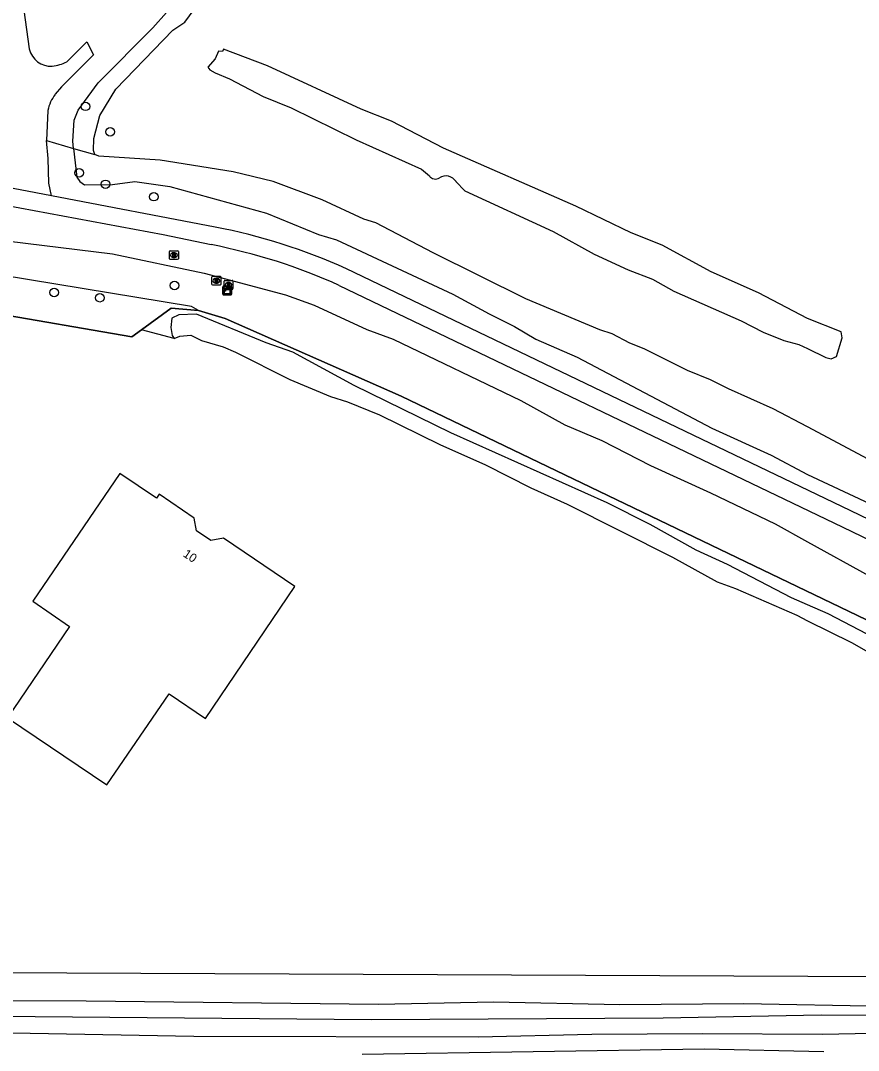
# Model space of a CAD drawing. Extents: x 162157 to 163165, y 378998 to 380775.
# Drawn here: x 162409.9 to 162505.8, y 379597.6 to 379715.5 of the extents above; entities that cross this region are included whole.
import ezdxf

# ---------------------------------------------------------------- set-up
doc = ezdxf.new("R2010")
doc.units = 0
for name, color, linetype in [('IMGEO_Boom', 7, 'Continuous'), ('IMGEO_Brandkraan', 7, 'Continuous'), ('IMGEO_Fietspad_gesloten', 7, 'Continuous'), ('IMGEO_Groenvoorziening', 7, 'Continuous'), ('IMGEO_Hek', 7, 'Continuous'), ('IMGEO_Kast', 7, 'Continuous'), ('IMGEO_Loofbos', 7, 'Continuous'), ('IMGEO_Muur', 7, 'Continuous'), ('IMGEO_Pand', 7, 'Continuous'), ('IMGEO_Pand_nummerreeks', 7, 'Continuous'), ('IMGEO_Rijbaan_lokaal_onverhard', 7, 'Continuous'), ('IMGEO_Rioolput', 7, 'Continuous'), ('IMGEO_Waterloop', 7, 'Continuous')]:
    doc.layers.add(name, color=color, linetype=linetype)

msp = doc.modelspace()

# ---------------------------------------------------------------- linework, layer by layer
at = {"layer": 'IMGEO_Boom'}
for centre in [(162417.36, 379705.69), (162420.18, 379702.78), (162416.63, 379698.09), (162419.64, 379696.77), (162425.19, 379695.35), (162427.56, 379685.19), (162413.77, 379684.37), (162419.01, 379683.78)]:
    msp.add_circle(centre, 0.489, dxfattribs=at)
at = {"layer": 'IMGEO_Brandkraan'}
for p, q in [((162426.99, 379688.24), (162426.99, 379689.09)), ((162427.06, 379689.16), (162427.91, 379689.16)), ((162427.99, 379689.09), (162427.99, 379688.24)), ((162427.91, 379688.16), (162427.06, 379688.16)), ((162427.5, 379688.38), (162427.47, 379688.38)), ((162427.48, 379688.94), (162427.5, 379688.94))]:
    msp.add_line(p, q, dxfattribs=at)
for points in [[(162426.99, 379688.24), (162426.99, 379689.09)], [(162427.06, 379689.16), (162427.91, 379689.16)], [(162427.99, 379689.09), (162427.99, 379688.24)], [(162427.91, 379688.16), (162427.06, 379688.16)], [(162427.33, 379688.86), (162427.33, 379688.46), (162427.55, 379688.46)], [(162427.57, 379688.86), (162427.33, 379688.86)], [(162427.51, 379688.78), (162427.46, 379688.78), (162427.46, 379688.71)], [(162427.46, 379688.71), (162427.51, 379688.71)], [(162427.52, 379688.63), (162427.46, 379688.63), (162427.46, 379688.55)], [(162427.46, 379688.55), (162427.52, 379688.55)]]:
    msp.add_lwpolyline(points, dxfattribs=at)
for centre, radius, start, end in [((162427.06, 379689.09), 0.0765, 91.552, 178.448), ((162427.06, 379689.09), 0.0765, 91.552, 178.448), ((162427.91, 379689.09), 0.0765, 1.552, 88.448), ((162427.91, 379689.09), 0.0765, 1.552, 88.448), ((162427.06, 379688.24), 0.0765, 181.552, 268.448), ((162427.06, 379688.24), 0.0765, 181.552, 268.448), ((162427.51, 379688.74), 0.0379, 267.8285, 90.9355), ((162427.52, 379688.59), 0.0404, 269.8759, 90.5077), ((162427.55, 379688.71), 0.251, 268.6676, 293.5347), ((162427.57, 379688.72), 0.145, 59.4692, 91.5367), ((162427.6, 379688.77), 0.0922, 285.5137, 58.1501), ((162427.6, 379688.57), 0.105, 301.3115, 78.989), ((162427.91, 379688.24), 0.0765, 271.552, 358.448), ((162427.91, 379688.24), 0.0765, 271.552, 358.448)]:
    msp.add_arc(centre, radius, start, end, dxfattribs=at)
for centre, major_axis, ratio, start_param, end_param in [((162427.47, 379688.66), (-0.387, 0.002), 0.722429, 4.712389, 7.853982), ((162427.5, 379688.66), (-0.39, 0.002), 0.717154, 1.570796, 4.712389)]:
    msp.add_ellipse(centre, major_axis=major_axis, ratio=ratio, start_param=start_param, end_param=end_param, dxfattribs=at)
at = {"layer": 'IMGEO_Fietspad_gesloten'}
for points in [[(162293.88, 379713.56), (162297.83, 379712.83), (162406.51, 379694.67), (162426.26, 379691.02), (162431.74, 379689.86)], [(162432.21, 379691.87), (162413.48, 379695.46)], [(162557.48, 379633.98), (162556.84, 379634.31), (162504.9, 379659.42), (162447.23, 379687.09)], [(162446.41, 379685.19), (162504, 379657.56), (162555.93, 379632.44), (162561.58, 379629.6)]]:
    msp.add_lwpolyline(points, dxfattribs=at)
for centre, radius, start, end in [((162419.44, 379625.71), 67.38, 65.6396, 79.0765), ((162418.79, 379623.79), 67.33, 65.7839, 78.9097)]:
    msp.add_arc(centre, radius, start, end, dxfattribs=at)
at = {"layer": 'IMGEO_Groenvoorziening'}
for points in [[(162423.76, 379680.09), (162422.68, 379679.3), (162406.25, 379682.13), (162347.07, 379692.29), (162343.87, 379688.35), (162342.56, 379688.42)], [(162430.28, 379682.33), (162427.17, 379682.58), (162423.76, 379680.09)], [(162427.51, 379679.13), (162423.76, 379680.09)], [(162217.87, 379605.5), (162247.08, 379605.11), (162255.15, 379605.08), (162262.9, 379605.2), (162282.05, 379605.15), (162289.85, 379605.22), (162308.4, 379605.53), (162313.87, 379605.74), (162332.41, 379605.9), (162337.03, 379605.95), (162352.97, 379606.09), (162363.72, 379605.88), (162374.72, 379605.85), (162378.4, 379605.96), (162380.44, 379606.31), (162381.21, 379606.63), (162576.44, 379605.74), (162576.49, 379606.38)], [(162583.87, 379601.63), (162573.91, 379602.07), (162557.68, 379602.05), (162525.01, 379602.55), (162508.94, 379602.64), (162492.71, 379602.92), (162478.54, 379602.81), (162464.08, 379603.1), (162450.91, 379602.84), (162417.45, 379603.23), (162402.03, 379603.27), (162387.27, 379603.21), (162374.55, 379603.06), (162361.54, 379603.25), (162327.73, 379603.13), (162310.18, 379603.37), (162273.39, 379603.64), (162254.33, 379604.29), (162234.09, 379604.68), (162224.23, 379605.14), (162217.88, 379605.23), (162217.87, 379605.5)], [(162501.89, 379597.42), (162488.2, 379597.72), (162449.03, 379597.12)]]:
    msp.add_lwpolyline(points, dxfattribs=at)
at = {"layer": 'IMGEO_Hek'}
for points in [[(162406.25, 379682.13), (162422.68, 379679.3), (162423.76, 379680.09)], [(162423.76, 379680.09), (162427.17, 379682.58), (162430.28, 379682.33)], [(162430.28, 379682.33), (162433.35, 379681.42), (162453.48, 379672.51), (162537.26, 379632.25), (162548.18, 379626.94), (162556.22, 379622.82), (162565.4, 379617.82), (162571.38, 379614.13), (162576.79, 379610.34)]]:
    msp.add_lwpolyline(points, dxfattribs=at)
at = {"layer": 'IMGEO_Kast'}
for p, q in [((162433.08, 379684.18), (162433.08, 379685.02)), ((162433.08, 379685.02), (162433.08, 379684.18)), ((162433.15, 379685.11), (162433.99, 379685.11)), ((162433.99, 379685.11), (162433.15, 379685.11)), ((162434.08, 379685.03), (162434.08, 379684.19)), ((162434.08, 379684.19), (162434.08, 379685.03)), ((162434, 379684.11), (162433.16, 379684.11)), ((162433.16, 379684.11), (162434, 379684.11))]:
    msp.add_line(p, q, dxfattribs=at)
for points in [[(162433.27, 379684.9), (162433.87, 379684.9), (162433.87, 379684.81), (162433.27, 379684.81), (162433.27, 379684.9)], [(162433.27, 379684.72), (162433.87, 379684.72), (162433.87, 379684.24), (162433.27, 379684.24), (162433.27, 379684.72)]]:
    msp.add_lwpolyline(points, dxfattribs=at)
msp.add_circle((162433.36, 379684.57), 0.0377, dxfattribs=at)
for centre, start, end in [((162433.16, 379685.03), 92.4484, 184.2845), ((162433.16, 379685.03), 92.4484, 184.2845), ((162434, 379685.03), 2.4484, 94.2845), ((162434, 379685.03), 2.4484, 94.2845), ((162433.16, 379684.19), 182.4484, 274.2845), ((162433.16, 379684.19), 182.4484, 274.2845), ((162434, 379684.19), 272.4484, 4.2845), ((162434, 379684.19), 272.4484, 4.2845)]:
    msp.add_arc(centre, 0.0779, start, end, dxfattribs=at)
at = {"layer": 'IMGEO_Loofbos'}
for points in [[(162412.89, 379701.78), (162415.99, 379700.88)], [(162430.28, 379682.33), (162429.51, 379682.78), (162345.56, 379696.61)], [(162406.42, 379690.54), (162420.47, 379688.81), (162430.94, 379686.6), (162440.24, 379684.12), (162443.52, 379682.91), (162449.55, 379680.16), (162452.58, 379679.03), (162467.18, 379672.02), (162472.24, 379669.23), (162476.49, 379667.45), (162482.03, 379664.56), (162488.91, 379661.45), (162496.32, 379657.89), (162500, 379655.84), (162507.07, 379651.92), (162527, 379642.12), (162536.23, 379637.93), (162571.68, 379620.55), (162577.82, 379616.97), (162589.02, 379609.76), (162590.32, 379608.63)], [(162576.79, 379610.34), (162571.38, 379614.13), (162565.4, 379617.82), (162556.22, 379622.82), (162548.18, 379626.94), (162537.26, 379632.25), (162453.48, 379672.51), (162433.35, 379681.42), (162430.28, 379682.33)]]:
    msp.add_lwpolyline(points, dxfattribs=at)
at = {"layer": 'IMGEO_Muur'}
msp.add_lwpolyline([(162381.21, 379606.63), (162576.44, 379605.74), (162576.49, 379606.38)], dxfattribs=at)
at = {"layer": 'IMGEO_Pand'}
msp.add_lwpolyline([(162408.42, 379635.69), (162419.81, 379628), (162426.95, 379638.44), (162431.1, 379635.6), (162441.34, 379650.7), (162433.15, 379656.25), (162431.71, 379655.98), (162430.06, 379657.09), (162429.79, 379658.54), (162425.79, 379661.28), (162425.48, 379660.81), (162421.29, 379663.64), (162411.33, 379649.02), (162415.52, 379646.14), (162408.42, 379635.69)], dxfattribs=at)
at = {"layer": 'IMGEO_Rijbaan_lokaal_onverhard'}
for points in [[(162407.91, 379787.07), (162404.33, 379784.27), (162403, 379782.61), (162402.58, 379781.28), (162405.36, 379754.24), (162407.92, 379733.94), (162410.93, 379712.28)], [(162415.21, 379710.79), (162417.5, 379713.07), (162418.27, 379711.58), (162414.63, 379707.93), (162413.9, 379707.07)], [(162413.05, 379705.23), (162412.89, 379701.78)], [(162413.48, 379695.46), (162413.18, 379696.91), (162413.08, 379699.72), (162412.89, 379701.78)], [(162413.48, 379695.46), (162407.26, 379696.65), (162406.55, 379696.77), (162403.9, 379697.22)]]:
    msp.add_lwpolyline(points, dxfattribs=at)
for centre, radius, start, end in [((162413.41, 379712.84), 2.55, 192.822, 273.2988), ((162413.15, 379714.75), 4.46, 275.2213, 297.5353), ((162417.24, 379704.4), 4.27, 141.4627, 168.8525)]:
    msp.add_arc(centre, radius, start, end, dxfattribs=at)
at = {"layer": 'IMGEO_Rioolput'}
for p, q in [((162431.84, 379685.31), (162431.84, 379686.16)), ((162431.92, 379686.24), (162432.77, 379686.24)), ((162432.33, 379686.01), (162432.36, 379686.01)), ((162432.85, 379686.16), (162432.85, 379685.31)), ((162433.23, 379684.83), (162433.23, 379685.68)), ((162433.31, 379685.75), (162434.16, 379685.75)), ((162434.23, 379685.68), (162434.23, 379684.83)), ((162432.77, 379685.23), (162431.92, 379685.23)), ((162432.35, 379685.46), (162432.33, 379685.46)), ((162434.16, 379684.75), (162433.31, 379684.75)), ((162433.72, 379685.53), (162433.75, 379685.53)), ((162433.74, 379684.97), (162433.72, 379684.97))]:
    msp.add_line(p, q, dxfattribs=at)
for points in [[(162431.84, 379685.31), (162431.84, 379686.16)], [(162431.92, 379686.24), (162432.77, 379686.24)], [(162432.43, 379685.93), (162432.18, 379685.93), (162432.18, 379685.53)], [(162432.18, 379685.53), (162432.31, 379685.53), (162432.31, 379685.7), (162432.32, 379685.7)], [(162432.36, 379685.85), (162432.31, 379685.85), (162432.31, 379685.77)], [(162432.31, 379685.77), (162432.36, 379685.77)], [(162432.36, 379685.67), (162432.43, 379685.53), (162432.57, 379685.53), (162432.51, 379685.66)], [(162432.85, 379686.16), (162432.85, 379685.31)], [(162433.23, 379684.83), (162433.23, 379685.68)], [(162433.31, 379685.75), (162434.16, 379685.75)], [(162434.23, 379685.68), (162434.23, 379684.83)], [(162432.77, 379685.23), (162431.92, 379685.23)], [(162434.16, 379684.75), (162433.31, 379684.75)], [(162433.82, 379685.45), (162433.57, 379685.45), (162433.57, 379685.05)], [(162433.57, 379685.05), (162433.69, 379685.05), (162433.69, 379685.21), (162433.71, 379685.21)], [(162433.75, 379685.37), (162433.69, 379685.37), (162433.69, 379685.29)], [(162433.69, 379685.29), (162433.75, 379685.29)], [(162433.75, 379685.18), (162433.82, 379685.05), (162433.96, 379685.05), (162433.9, 379685.18)]]:
    msp.add_lwpolyline(points, dxfattribs=at)
for centre, radius, start, end in [((162431.92, 379686.16), 0.0765, 91.552, 178.448), ((162431.92, 379686.16), 0.0765, 91.552, 178.448), ((162432.31, 379685.64), 0.0533, 26.0293, 88.6989), ((162432.36, 379685.76), 0.0964, 77.0061, 93.1865), ((162432.34, 379685.96), 0.19, 274.7715, 282.9687), ((162432.38, 379685.81), 0.0378, 276.6634, 79.6772), ((162432.43, 379685.82), 0.109, 350.3612, 89.416), ((162432.43, 379685.82), 0.112, 277.5842, 350.9817), ((162432.41, 379685.61), 0.108, 29.5134, 73.7905), ((162432.77, 379686.16), 0.0765, 1.552, 88.448), ((162432.77, 379686.16), 0.0765, 1.552, 88.448), ((162433.31, 379685.68), 0.0765, 91.552, 178.448), ((162433.31, 379685.68), 0.0765, 91.552, 178.448), ((162434.16, 379685.68), 0.0765, 1.552, 88.448), ((162434.16, 379685.68), 0.0765, 1.552, 88.448), ((162431.92, 379685.31), 0.0765, 181.552, 268.448), ((162431.92, 379685.31), 0.0765, 181.552, 268.448), ((162432.77, 379685.31), 0.0765, 271.552, 358.448), ((162432.77, 379685.31), 0.0765, 271.552, 358.448), ((162433.31, 379684.83), 0.0765, 181.552, 268.448), ((162433.31, 379684.83), 0.0765, 181.552, 268.448), ((162433.7, 379685.16), 0.0533, 26.0293, 88.6989), ((162433.75, 379685.27), 0.0964, 77.0061, 93.1865), ((162433.73, 379685.48), 0.19, 274.7715, 282.9687), ((162433.77, 379685.33), 0.0378, 276.6634, 79.6772), ((162433.82, 379685.34), 0.109, 350.3612, 89.416), ((162433.82, 379685.34), 0.112, 277.5842, 350.9817), ((162433.8, 379685.12), 0.108, 29.5134, 73.7905), ((162434.16, 379684.83), 0.0765, 271.552, 358.448), ((162434.16, 379684.83), 0.0765, 271.552, 358.448)]:
    msp.add_arc(centre, radius, start, end, dxfattribs=at)
for centre, major_axis, ratio, start_param, end_param in [((162432.33, 379685.73), (-0.387, 0.002), 0.722429, 4.712389, 7.853982), ((162432.36, 379685.73), (-0.39, 0.002), 0.717154, 1.570796, 4.712389), ((162433.72, 379685.25), (-0.387, 0.002), 0.722429, 4.712389, 7.853982), ((162433.74, 379685.25), (-0.39, 0.002), 0.717154, 1.570796, 4.712389)]:
    msp.add_ellipse(centre, major_axis=major_axis, ratio=ratio, start_param=start_param, end_param=end_param, dxfattribs=at)
at = {"layer": 'IMGEO_Waterloop'}
for points in [[(162418.41, 379700.17), (162418.29, 379700.63), (162418.33, 379702.03), (162419.01, 379704.63), (162420.85, 379707.67), (162427.37, 379714.42), (162428.73, 379715.33), (162429.81, 379716.79), (162431.87, 379718.53), (162435.73, 379722.44), (162436.81, 379724.52), (162437.81, 379727.6), (162438.09, 379730.39), (162437.87, 379732.15), (162436.61, 379736.13), (162434.68, 379739.75), (162433.34, 379741.62), (162431.94, 379744.12), (162431.35, 379745.64), (162430.75, 379748.23), (162430.6, 379750), (162430.81, 379753.63), (162433.19, 379759.73)], [(162415.99, 379700.88), (162415.9, 379701.72), (162416.07, 379704.11), (162416.53, 379705.25), (162418.82, 379708.37), (162425.07, 379714.68), (162428.19, 379718.23), (162429.87, 379719.79), (162431.45, 379721.79), (162433.88, 379726.03), (162434.41, 379727.38), (162434.93, 379729.62), (162434.96, 379731.45), (162434.82, 379732.58), (162434.21, 379734.79), (162431.84, 379739.92), (162430.72, 379741.38), (162429.29, 379744.28), (162428.39, 379748.48), (162428.43, 379750), (162428.47, 379751.52)], [(162459.77, 379697.07), (162460.78, 379696.01), (162470.9, 379691.35), (162475.6, 379688.76), (162479.47, 379686.98), (162482.26, 379685.92), (162484.72, 379684.55), (162492.41, 379681.12), (162494.95, 379679.84), (162497.3, 379678.9), (162499.02, 379678.44), (162500, 379677.97), (162502.13, 379676.94), (162502.74, 379676.79), (162503.32, 379677.05), (162503.98, 379679.17), (162503.86, 379679.87), (162500, 379681.42), (162494.39, 379684.33), (162488.98, 379686.75), (162483.39, 379689.79), (162479.83, 379691.22), (162473.48, 379694.26), (162458.35, 379700.92), (162452.41, 379704.01), (162448.92, 379705.39), (162438.21, 379710.32), (162433.16, 379712.25), (162433.03, 379711.98), (162432.6, 379712.03), (162432.21, 379711.14), (162431.36, 379710.19), (162431.61, 379709.88), (162432.22, 379709.52), (162433.86, 379708.86), (162437.69, 379706.82), (162440.91, 379705.54), (162448.35, 379701.85), (162455.84, 379698.5), (162456.73, 379697.74)], [(162415.99, 379700.88), (162418.41, 379700.17)], [(162415.99, 379700.88), (162416.35, 379697.6), (162416.72, 379697.08), (162417.25, 379696.71), (162420.45, 379696.73), (162423.01, 379697.07), (162427.01, 379696.5), (162438.08, 379693.47), (162444.05, 379691.02), (162446.1, 379690.4), (162459.42, 379684.2), (162463.56, 379681.92), (162466.49, 379680.5), (162468.93, 379679.03), (162473.64, 379676.97), (162489.06, 379668.85), (162495.85, 379665.75), (162500, 379663.53), (162509.49, 379659.13)], [(162525.17, 379656.9), (162522.66, 379657.86), (162516.28, 379660.79), (162512.53, 379662.77), (162508.68, 379664.39), (162500, 379668.98), (162496.1, 379671.04), (162490.98, 379673.33), (162488.93, 379674.39), (162486.27, 379675.43), (162481.32, 379677.92), (162479.66, 379678.58), (162477.66, 379679.66), (162476.24, 379680.12), (162467.78, 379683.67), (162457.18, 379688.91), (162450.6, 379692.37), (162449.24, 379692.79), (162444.45, 379695), (162438.86, 379697.09), (162434.27, 379698.21), (162425.92, 379699.54), (162418.87, 379700), (162418.41, 379700.17)], [(162526.23, 379634.14), (162526.72, 379635.02), (162526.82, 379635.76), (162525.74, 379636.78), (162522.64, 379638.06), (162506.86, 379645.24), (162502.39, 379647.6), (162500, 379648.62), (162498.17, 379649.41), (162490.86, 379653.23), (162487.26, 379654.89), (162482.01, 379657.8), (162477.08, 379660.29), (162459.17, 379668.3), (162448.12, 379673.72), (162441.1, 379677.53), (162438.03, 379678.63), (162430.05, 379681.9), (162428.03, 379681.84), (162427.24, 379681.45), (162427.13, 379680.38), (162427.28, 379679.47), (162427.51, 379679.13)], [(162427.51, 379679.13), (162428.15, 379679.38), (162429.43, 379679.48), (162430.65, 379678.9), (162433.12, 379678.16), (162434.55, 379677.53), (162440.74, 379674.41), (162445.4, 379672.46), (162447.34, 379671.86), (162451, 379670.36), (162457.94, 379666.98), (162463.16, 379664.66), (162468.34, 379662), (162472.51, 379660.13), (162484.57, 379654.08), (162489.68, 379651.24), (162491.76, 379650.47), (162498.81, 379647.43), (162500, 379646.77), (162505.07, 379644.31), (162510.75, 379641.07)], [(162390.14, 379601.66), (162450.09, 379601.12), (162483.49, 379601.33), (162501.57, 379601.68), (162517.5, 379601.59), (162533.57, 379601.39), (162564.43, 379600.52), (162577.81, 379600.87), (162587.65, 379600.27), (162599.79, 379599)], [(162582.36, 379597.47), (162571.83, 379598.01), (162559.51, 379598.29), (162513.07, 379599.65), (162501.71, 379599.4), (162488, 379599.51), (162475.33, 379599.41), (162462.3, 379599.1), (162429.76, 379599.2), (162406.83, 379599.61)]]:
    msp.add_lwpolyline(points, dxfattribs=at)
for centre, radius, start, end in [((162457.42, 379698.18), 0.82, 213.2112, 304.3225), ((162458.61, 379696.34), 1.38, 32.0229, 121.8774)]:
    msp.add_arc(centre, radius, start, end, dxfattribs=at)

# ---------------------------------------------------------------- texts
at = {"layer": 'IMGEO_Pand_nummerreeks'}
msp.add_text('10', height=1, rotation=326.078, dxfattribs=at).set_placement((162428.45, 379654.22))

doc.saveas('drawing.dxf')
